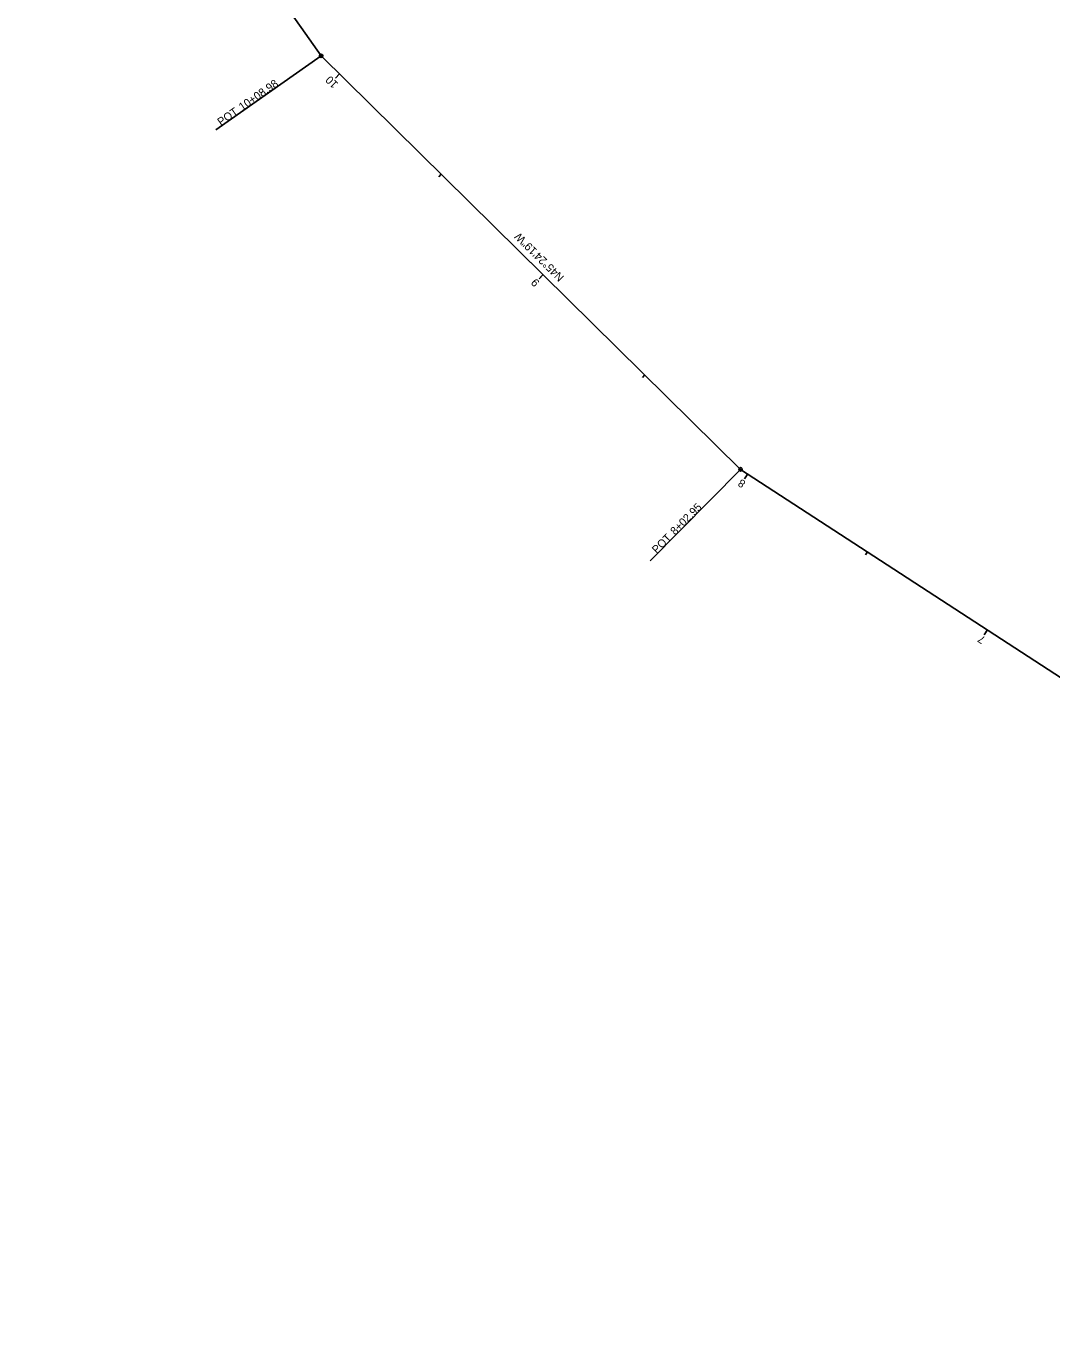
# Model space of a CAD drawing. Extents: x 2195310 to 2196150, y 661045 to 662024.
# Drawn here: x 2195432.4 to 2195791.1, y 661082.8 to 661542.1 of the extents above; entities that cross this region are included whole.
import ezdxf

# ---------------------------------------------------------------- set-up
doc = ezdxf.new("R2010")
doc.units = 0
for name, color, linetype in [('Default', 7, 'Continuous'), ('GE_X_Alignment', 7, 'Continuous'), ('GE_X_Alignment_1000_Stations', 7, 'Continuous'), ('GE_X_Alignment_100_Stations', 7, 'Continuous'), ('GE_X_Alignment_500_Stations', 7, 'Continuous')]:
    doc.layers.add(name, color=color, linetype=linetype)

msp = doc.modelspace()

# ---------------------------------------------------------------- linework, layer by layer
at = {"layer": 'Default'}
for centre in [(2195535.54, 661531.67), (2195535.54, 661531.67), (2195535.54, 661531.67), (2195541.93, 661525.37), (2195541.93, 661525.37), (2195541.93, 661525.37), (2195608.89, 661459.35), (2195608.89, 661459.35), (2195608.89, 661459.35), (2195608.89, 661459.35), (2195608.89, 661459.35), (2195608.89, 661459.35), (2195613.14, 661455.16), (2195682.25, 661387.02), (2195682.25, 661387.02), (2195682.25, 661387.02), (2195684.72, 661385.41), (2195768.51, 661330.82)]:
    msp.add_circle(centre, 0.0000833, dxfattribs=at)
at = {"layer": 'GE_X_Alignment'}
for p, q in [((2195535.54, 661531.67), (2195432.42, 661678.35)), ((2195682.25, 661387.02), (2195535.54, 661531.67)), ((2196149.1, 661082.85), (2195682.25, 661387.02))]:
    msp.add_line(p, q, dxfattribs=at)
at = {"layer": 'GE_X_Alignment_1000_Stations'}
for p, q in [((2195535.54, 661531.67), (2195498.72, 661505.79)), ((2195541.93, 661525.37), (2195540.53, 661523.94)), ((2195682.25, 661387.02), (2195650.65, 661354.98))]:
    msp.add_line(p, q, dxfattribs=at)
for centre in [(2195535.54, 661531.67), (2195682.25, 661387.02)]:
    msp.add_circle(centre, 0.6, dxfattribs=at)
at = {"layer": 'GE_X_Alignment_100_Stations'}
for p, q in [((2195535.54, 661531.67), (2195498.72, 661505.79)), ((2195541.93, 661525.37), (2195540.53, 661523.94)), ((2195577.54, 661490.26), (2195576.69, 661489.41)), ((2195613.14, 661455.16), (2195611.74, 661453.73)), ((2195648.75, 661420.05), (2195647.9, 661419.2)), ((2195682.25, 661387.02), (2195650.65, 661354.98)), ((2195684.72, 661385.41), (2195683.63, 661383.74)), ((2195726.61, 661358.12), (2195725.96, 661357.11)), ((2195768.51, 661330.82), (2195767.41, 661329.15))]:
    msp.add_line(p, q, dxfattribs=at)
for centre in [(2195535.54, 661531.67), (2195682.25, 661387.02)]:
    msp.add_circle(centre, 0.6, dxfattribs=at)
at = {"layer": 'GE_X_Alignment_500_Stations'}
for p, q in [((2195535.54, 661531.67), (2195498.72, 661505.79)), ((2195541.93, 661525.37), (2195540.53, 661523.94)), ((2195613.14, 661455.16), (2195612.3, 661454.3)), ((2195682.25, 661387.02), (2195650.65, 661354.98)), ((2195684.72, 661385.41), (2195684.07, 661384.41)), ((2195768.51, 661330.82), (2195767.85, 661329.82))]:
    msp.add_line(p, q, dxfattribs=at)
for centre in [(2195535.54, 661531.67), (2195682.25, 661387.02)]:
    msp.add_circle(centre, 0.6, dxfattribs=at)

# ---------------------------------------------------------------- texts
at = {"layer": 'GE_X_Alignment_1000_Stations'}
for s, rotation, p in [('10+08.98', 35.1079, (2195507.97, 661512.35)), ('10', 135.4052, (2195541.71, 661522.01)), ('POT', 35.1079, (2195500.5, 661507.1)), ('N45°24\'19"W', 135.4052, (2195620.71, 661454.44)), ('8+02.95', 45.4052, (2195659.33, 661363.85)), ('POT', 45.4052, (2195652.92, 661357.35))]:
    msp.add_text(s, height=2.8, rotation=rotation, dxfattribs=at).set_placement(p)
at = {"layer": 'GE_X_Alignment_100_Stations'}
for s, rotation, p in [('10+08.98', 35.1079, (2195507.97, 661512.35)), ('10', 135.4052, (2195541.71, 661522.01)), ('POT', 35.1079, (2195500.5, 661507.1)), ('N45°24\'19"W', 135.4052, (2195620.71, 661454.44)), ('9', 135.4052, (2195612.12, 661452.59)), ('8', 146.914, (2195684.26, 661382.67)), ('8+02.95', 45.4052, (2195659.33, 661363.85)), ('POT', 45.4052, (2195652.92, 661357.35)), ('7', 146.914, (2195768.12, 661328.09))]:
    msp.add_text(s, height=2.8, rotation=rotation, dxfattribs=at).set_placement(p)
at = {"layer": 'GE_X_Alignment_500_Stations'}
for s, rotation, p in [('10+08.98', 35.1079, (2195507.97, 661512.35)), ('10', 135.4052, (2195541.71, 661522.01)), ('POT', 35.1079, (2195500.5, 661507.1)), ('N45°24\'19"W', 135.4052, (2195620.71, 661454.44)), ('8+02.95', 45.4052, (2195659.33, 661363.85)), ('POT', 45.4052, (2195652.92, 661357.35))]:
    msp.add_text(s, height=2.8, rotation=rotation, dxfattribs=at).set_placement(p)

doc.saveas('drawing.dxf')
